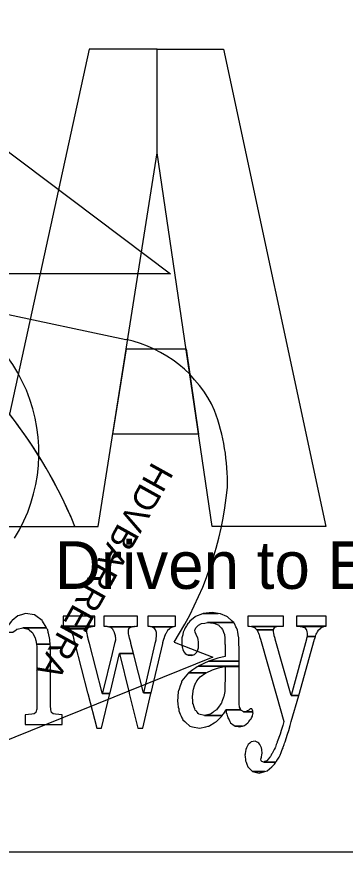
# Model space of a CAD drawing. Extents: x -0.5 to 21.6, y 4.3 to 17.8.
# Drawn here: x 0.949 to 1.229, y 5.937 to 6.651 of the extents above; entities that cross this region are included whole.
import ezdxf

# ---------------------------------------------------------------- set-up
doc = ezdxf.new("R2010")
doc.units = 0
for name, color, linetype in [('DETL-LINE', 7, 'Continuous'), ('TTLB-TEXT', 7, 'Continuous'), ('USER-BORD', 7, 'Continuous')]:
    doc.layers.add(name, color=color, linetype=linetype)

msp = doc.modelspace()

# ---------------------------------------------------------------- linework, layer by layer
at = {"layer": 'DETL-LINE'}
msp.add_line((0.88856, 6.21553), (0.99861, 6.21553), dxfattribs=at)
for points in [[(0.3943, 14.1527), (0.3943, 16.2906), (7.7685, 16.2906), (7.7685, 5.9375), (0.3943, 5.9375), (0.3943, 13.6862)], [(0.99861, 6.21553), (1.01854, 6.21553), (1.0688, 6.53442), (1.0688, 6.62281), (1.01074, 6.62281), (0.94281, 6.31145)]]:
    msp.add_lwpolyline(points, dxfattribs=at)
for points in [[(1.0688, 6.53442), (1.0688, 6.62281), (1.12513, 6.62281), (1.21244, 6.21553), (1.11559, 6.21553)], [(1.04243, 6.36709), (1.09335, 6.36709), (1.10403, 6.29434), (1.03096, 6.29434)], [(0.9395, 6.1274), (0.9384, 6.1254), (0.9456, 6.1254), (0.9484, 6.1274), (0.9492, 6.1279), (0.9494, 6.128), (0.9494, 6.128), (0.9542, 6.129), (0.9744, 6.129), (0.9742, 6.1295), (0.9711, 6.1348), (0.9708, 6.1353), (0.9653, 6.1393), (0.9641, 6.1401), (0.9565, 6.1412), (0.953, 6.1401), (0.95, 6.1393), (0.9452, 6.1353), (0.9445, 6.1348), (0.9406, 6.1295), (0.9403, 6.129), (0.9399, 6.128), (0.9399, 6.1279)], [(1.0939, 6.1062), (1.095, 6.1056), (1.0987, 6.1056), (1.1004, 6.1062), (1.1012, 6.107), (1.1025, 6.1084), (1.1032, 6.1104), (1.1038, 6.112), (1.1038, 6.1126), (1.1038, 6.1144), (1.1039, 6.1153), (1.1039, 6.1153), (1.1039, 6.1154), (1.1039, 6.1164), (1.1035, 6.1194), (1.1033, 6.12), (1.1033, 6.1204), (1.1032, 6.1204), (1.1019, 6.1232), (1.1019, 6.1234), (1.101, 6.1252), (1.101, 6.1252), (1.1008, 6.127), (1.1008, 6.127), (1.101, 6.1276), (1.1015, 6.1289), (1.1025, 6.13), (1.1032, 6.1307), (1.1039, 6.1312), (1.1064, 6.1326), (1.1092, 6.1331), (1.1115, 6.1335), (1.134, 6.1335), (1.1327, 6.1347), (1.1287, 6.1384), (1.128, 6.1387), (1.1225, 6.141), (1.1207, 6.1413), (1.1079, 6.1413), (1.1072, 6.141), (1.1014, 6.1387), (1.1011, 6.1384), (1.0965, 6.1347), (1.0956, 6.1335), (1.0953, 6.1331), (1.0949, 6.1326), (1.0939, 6.1312), (1.0936, 6.1307), (1.093, 6.13), (1.0925, 6.1289), (1.0919, 6.1276), (1.0917, 6.127), (1.0916, 6.127), (1.0909, 6.1252), (1.0908, 6.1252), (1.0905, 6.1234), (1.0905, 6.1232), (1.0898, 6.1204), (1.0898, 6.1204), (1.0898, 6.12), (1.0897, 6.1194), (1.0896, 6.1164), (1.0896, 6.1154), (1.0896, 6.1153), (1.0897, 6.1144), (1.0901, 6.1126), (1.0902, 6.112), (1.0905, 6.1104), (1.0917, 6.1084), (1.0925, 6.107)], [(1.1156, 6.1421), (1.1079, 6.1413), (1.1207, 6.1413)], [(0.9885, 6.1389), (0.9885, 6.1304), (1.0155, 6.1304), (1.0155, 6.1389)], [(1.0275, 6.13), (1.0282, 6.1299), (1.0467, 6.1299), (1.0473, 6.13), (1.0477, 6.1301), (1.0479, 6.1302), (1.0493, 6.1302), (1.0492, 6.1302), (1.0506, 6.1304), (1.0506, 6.1304), (1.0519, 6.1304), (1.0519, 6.1389), (1.0233, 6.1389), (1.0233, 6.1304), (1.0258, 6.1304), (1.0263, 6.1302), (1.0268, 6.1302), (1.027, 6.1301)], [(1.0638, 6.1301), (1.0643, 6.13), (1.0821, 6.13), (1.0823, 6.1301), (1.0826, 6.1302), (1.0832, 6.1302), (1.0838, 6.1304), (1.0844, 6.1304), (1.0844, 6.1389), (1.0608, 6.1389), (1.0608, 6.1304), (1.0624, 6.1304), (1.0629, 6.1302), (1.0635, 6.1302)], [(1.1204, 6.1032), (1.1126, 6.1006), (1.1385, 6.1006), (1.1385, 6.1032), (1.1385, 6.1047), (1.1385, 6.1053), (1.1385, 6.1056), (1.1385, 6.1062), (1.1385, 6.107), (1.1385, 6.1084), (1.1385, 6.1104), (1.1385, 6.112), (1.1385, 6.1126), (1.1384, 6.1144), (1.1384, 6.1153), (1.1384, 6.1154), (1.1384, 6.1164), (1.1383, 6.1194), (1.1383, 6.1194), (1.1383, 6.12), (1.1383, 6.1204), (1.1383, 6.1204), (1.1378, 6.1232), (1.1378, 6.1234), (1.1375, 6.1252), (1.1375, 6.1252), (1.1372, 6.127), (1.1372, 6.127), (1.137, 6.1276), (1.1369, 6.1276), (1.1363, 6.1289), (1.1357, 6.13), (1.1353, 6.1307), (1.1352, 6.1312), (1.1345, 6.1326), (1.1342, 6.1331), (1.134, 6.1335), (1.1115, 6.1335), (1.1168, 6.1331), (1.1179, 6.1326), (1.1212, 6.1312), (1.1216, 6.1307), (1.1223, 6.13), (1.1232, 6.1289), (1.1244, 6.1276), (1.1247, 6.127), (1.1247, 6.127), (1.1253, 6.1252), (1.1253, 6.1252), (1.126, 6.1234), (1.1261, 6.1232), (1.1264, 6.1204), (1.1264, 6.1204), (1.1264, 6.12), (1.1264, 6.1194), (1.1264, 6.1164), (1.1264, 6.1154), (1.1264, 6.1153), (1.1265, 6.1144), (1.1265, 6.1126), (1.1265, 6.112), (1.1265, 6.1104), (1.1265, 6.1084), (1.1265, 6.107), (1.1265, 6.1062), (1.1265, 6.1056), (1.1265, 6.1053), (1.1265, 6.1047)], [(1.1474, 6.1304), (1.149, 6.1302), (1.1705, 6.1302), (1.1706, 6.1304), (1.1727, 6.1304), (1.1763, 6.1305), (1.1763, 6.1389), (1.1458, 6.1389), (1.1458, 6.1305), (1.1458, 6.1304)], [(1.1875, 6.1305), (1.1875, 6.1304), (1.2126, 6.1304), (1.2126, 6.1305), (1.2126, 6.1389), (1.1875, 6.1389)], [(0.9652, 6.1183), (0.9658, 6.1151), (0.9775, 6.1151), (0.9773, 6.1183), (0.9772, 6.1191), (0.977, 6.1204), (0.9763, 6.1232), (0.976, 6.1246), (0.9759, 6.1249), (0.9758, 6.1254), (0.9758, 6.1254), (0.9754, 6.1274), (0.975, 6.1279), (0.975, 6.128), (0.9744, 6.129), (0.9542, 6.129), (0.9588, 6.128), (0.9589, 6.1279), (0.9596, 6.1274), (0.962, 6.1254), (0.9625, 6.1249), (0.9627, 6.1246), (0.9634, 6.1232), (0.9648, 6.1204), (0.965, 6.1191)], [(0.9918, 6.1299), (0.9922, 6.1298), (1.0111, 6.1298), (1.0115, 6.1299), (1.0122, 6.13), (1.0126, 6.1301), (1.0128, 6.1302), (1.0137, 6.1302), (1.0137, 6.1302), (1.0145, 6.1304), (1.0145, 6.1304), (1.0155, 6.1304), (0.9885, 6.1304), (0.9893, 6.1304), (0.9902, 6.1302), (0.9905, 6.1302), (0.9908, 6.1301), (0.9912, 6.13)], [(0.9941, 6.1285), (0.9944, 6.1282), (1.0092, 6.1282), (1.0092, 6.1285), (1.0094, 6.1287), (1.0095, 6.1289), (1.0097, 6.129), (1.0109, 6.1298), (1.0111, 6.1298), (0.9921, 6.1298), (0.9923, 6.1298), (0.9934, 6.129), (0.9935, 6.1289), (0.9937, 6.1287)], [(1.0095, 6.0731), (1.0172, 6.0433), (1.0213, 6.0433), (1.0284, 6.0731), (1.0219, 6.0731), (1.0217, 6.0735), (1.0109, 6.1157), (1.0107, 6.1166), (1.0102, 6.1186), (1.01, 6.1194), (1.0099, 6.1196), (1.0098, 6.12), (1.0094, 6.1219), (1.0093, 6.1221), (1.0092, 6.1226), (1.0089, 6.1241), (1.0087, 6.1245), (1.0087, 6.1248), (1.0087, 6.1253), (1.0087, 6.127), (1.0087, 6.127), (1.0087, 6.1272), (1.0092, 6.1282), (0.9944, 6.1282), (0.9949, 6.1272), (0.995, 6.127), (0.9951, 6.127), (0.9959, 6.1253), (0.996, 6.1248), (0.9961, 6.1245), (0.9963, 6.1241), (0.9968, 6.1226), (0.997, 6.1221), (0.997, 6.1219), (0.9975, 6.12), (0.9976, 6.1196), (0.9976, 6.1194), (0.9978, 6.1186), (0.9984, 6.1166), (0.9986, 6.1157), (1.0094, 6.0735)], [(1.022, 6.0735), (1.0219, 6.0731), (1.0284, 6.0731), (1.0285, 6.0735), (1.0366, 6.1072), (1.0484, 6.1072), (1.0463, 6.1157), (1.0463, 6.1157), (1.0461, 6.1166), (1.0456, 6.1186), (1.0456, 6.1186), (1.0453, 6.1194), (1.0453, 6.1196), (1.0452, 6.12), (1.0448, 6.1219), (1.0447, 6.1221), (1.0446, 6.1226), (1.0443, 6.1241), (1.0442, 6.1245), (1.0442, 6.1248), (1.0442, 6.1253), (1.0442, 6.127), (1.0442, 6.127), (1.0442, 6.1272), (1.0446, 6.1282), (1.0446, 6.1285), (1.0448, 6.1287), (1.045, 6.1289), (1.0451, 6.129), (1.0451, 6.129), (1.0462, 6.1298), (1.0464, 6.1298), (1.0467, 6.1299), (1.0282, 6.1299), (1.0283, 6.1298), (1.0285, 6.1298), (1.0296, 6.129), (1.0298, 6.1289), (1.03, 6.1287), (1.0304, 6.1285), (1.0305, 6.1282), (1.031, 6.1272), (1.0311, 6.127), (1.0312, 6.127), (1.0319, 6.1253), (1.0321, 6.1248), (1.0322, 6.1245), (1.0323, 6.1241), (1.0328, 6.1226), (1.0329, 6.1221), (1.0329, 6.1219), (1.0333, 6.12), (1.0334, 6.1196), (1.0333, 6.1194), (1.0331, 6.1186), (1.0326, 6.1166), (1.0324, 6.1157), (1.0303, 6.1072)], [(1.0667, 6.1157), (1.057, 6.0735), (1.0635, 6.0735), (1.0734, 6.1157), (1.0736, 6.1166), (1.0741, 6.1186), (1.0743, 6.1194), (1.0743, 6.1194), (1.0744, 6.1196), (1.0745, 6.12), (1.0753, 6.1219), (1.0753, 6.1221), (1.0756, 6.1226), (1.0755, 6.1226), (1.0762, 6.1241), (1.0764, 6.1245), (1.0764, 6.1245), (1.0765, 6.1248), (1.0768, 6.1253), (1.0778, 6.127), (1.0779, 6.127), (1.0779, 6.1272), (1.0792, 6.1282), (1.0795, 6.1285), (1.0798, 6.1287), (1.0799, 6.1289), (1.0801, 6.129), (1.0816, 6.1298), (1.0817, 6.1298), (1.0819, 6.1299), (1.0821, 6.13), (1.0643, 6.13), (1.0645, 6.1299), (1.0646, 6.1298), (1.0647, 6.1298), (1.0659, 6.129), (1.066, 6.1289), (1.0661, 6.1287), (1.0663, 6.1285), (1.0664, 6.1282), (1.0671, 6.1272), (1.0671, 6.127), (1.0672, 6.127), (1.0677, 6.1253), (1.0679, 6.1248), (1.0679, 6.1245), (1.0679, 6.1241), (1.0679, 6.1226), (1.0679, 6.1221), (1.0679, 6.1219), (1.0676, 6.12), (1.0675, 6.1196), (1.0675, 6.1194), (1.0674, 6.1186), (1.0669, 6.1166)], [(1.1534, 6.1276), (1.1538, 6.1272), (1.1678, 6.1272), (1.1679, 6.1276), (1.1686, 6.1291), (1.1686, 6.1293), (1.1687, 6.1293), (1.1689, 6.1296), (1.1697, 6.13), (1.1705, 6.1302), (1.149, 6.1302), (1.1498, 6.13), (1.1507, 6.1296), (1.1518, 6.1293), (1.1518, 6.1293), (1.152, 6.1291)], [(1.1605, 6.0149), (1.1595, 6.0145), (1.1698, 6.0145), (1.1701, 6.0149), (1.1705, 6.0156), (1.1707, 6.0159), (1.1714, 6.017), (1.1725, 6.0188), (1.1728, 6.0193), (1.1734, 6.0205), (1.1738, 6.0211), (1.1741, 6.0219), (1.1753, 6.0253), (1.1759, 6.0267), (1.1758, 6.0267), (1.176, 6.0271), (1.1769, 6.0294), (1.1773, 6.0306), (1.1775, 6.0311), (1.1777, 6.0317), (1.1798, 6.0384), (1.1808, 6.0415), (1.182, 6.0458), (1.1829, 6.049), (1.1829, 6.049), (1.1893, 6.0714), (1.1829, 6.0714), (1.1692, 6.1194), (1.1692, 6.1196), (1.1691, 6.1196), (1.1691, 6.12), (1.1686, 6.1216), (1.1685, 6.1219), (1.1683, 6.123), (1.1681, 6.1237), (1.168, 6.1244), (1.168, 6.1246), (1.1678, 6.1256), (1.1678, 6.1271), (1.1678, 6.1272), (1.1538, 6.1272), (1.1538, 6.1271), (1.1545, 6.1256), (1.155, 6.1246), (1.1551, 6.1244), (1.1553, 6.1237), (1.1556, 6.123), (1.156, 6.1219), (1.156, 6.1216), (1.1565, 6.12), (1.1566, 6.1196), (1.1567, 6.1194), (1.1703, 6.0714), (1.1766, 6.049), (1.1758, 6.0458), (1.1744, 6.0415), (1.1735, 6.0384), (1.171, 6.0317), (1.1708, 6.0311), (1.1706, 6.0306), (1.1701, 6.0294), (1.1694, 6.0271), (1.1691, 6.0267), (1.1684, 6.0253), (1.1666, 6.0219), (1.1662, 6.0211), (1.1659, 6.0205), (1.1653, 6.0193), (1.1648, 6.0188), (1.1632, 6.017), (1.1623, 6.0159), (1.162, 6.0156)], [(1.189, 6.1304), (1.1905, 6.1302), (1.2107, 6.1302), (1.2116, 6.1304), (1.2126, 6.1304), (1.1875, 6.1304)], [(1.1964, 6.1219), (1.1964, 6.1216), (1.2036, 6.1216), (1.2037, 6.1219), (1.204, 6.123), (1.2042, 6.1237), (1.2046, 6.1244), (1.2047, 6.1246), (1.2053, 6.1256), (1.2061, 6.1271), (1.2062, 6.1272), (1.2067, 6.1276), (1.2083, 6.1291), (1.2084, 6.1293), (1.2085, 6.1293), (1.2085, 6.1293), (1.2093, 6.1296), (1.21, 6.13), (1.2107, 6.1302), (1.1905, 6.1302), (1.1923, 6.13), (1.1931, 6.1296), (1.1941, 6.1293), (1.1942, 6.1293), (1.1945, 6.1291), (1.1957, 6.1276), (1.196, 6.1272), (1.196, 6.1271), (1.1963, 6.1256), (1.1965, 6.1246), (1.1965, 6.1244), (1.1965, 6.1237), (1.1965, 6.123)], [(1.1959, 6.1194), (1.1829, 6.0714), (1.1893, 6.0714), (1.2028, 6.1194), (1.2029, 6.1196), (1.203, 6.12), (1.2036, 6.1216), (1.1964, 6.1216), (1.196, 6.12), (1.196, 6.1196)], [(0.9563, 6.0549), (0.9563, 6.0465), (0.9877, 6.0465), (0.9877, 6.0549), (0.9821, 6.0553), (0.9801, 6.0556), (0.9787, 6.0567), (0.978, 6.059), (0.978, 6.059), (0.978, 6.0593), (0.978, 6.0593), (0.9778, 6.0626), (0.9778, 6.0956), (0.9778, 6.1029), (0.9778, 6.1094), (0.9778, 6.1102), (0.9778, 6.1102), (0.9778, 6.1106), (0.9777, 6.1127), (0.9775, 6.1151), (0.9658, 6.1151), (0.966, 6.1127), (0.9661, 6.1106), (0.9662, 6.1102), (0.9662, 6.1094), (0.9662, 6.1029), (0.9662, 6.0956), (0.9662, 6.0626), (0.966, 6.0593), (0.9659, 6.059), (0.9659, 6.059), (0.9653, 6.0567), (0.9639, 6.0556), (0.9618, 6.0553)], [(1.0449, 6.0731), (1.0522, 6.0433), (1.0564, 6.0433), (1.0633, 6.0731), (1.0635, 6.0735), (1.057, 6.0735), (1.0484, 6.1072), (1.0366, 6.1072), (1.0448, 6.0735)], [(1.095, 6.1056), (1.0978, 6.1053), (1.0987, 6.1056)], [(1.0956, 6.0907), (1.0953, 6.0906), (1.1102, 6.0906), (1.1105, 6.0907), (1.1159, 6.0932), (1.121, 6.0949), (1.1247, 6.0958), (1.1265, 6.0961), (1.1385, 6.0961), (1.1385, 6.0964), (1.1036, 6.0964), (1.1033, 6.0961), (1.1028, 6.0958), (1.1015, 6.0949), (1.0991, 6.0932)], [(1.1126, 6.1006), (1.1036, 6.0964), (1.1385, 6.0964), (1.1385, 6.1006)], [(1.0988, 6.0446), (1.1048, 6.0433), (1.1102, 6.0446), (1.1121, 6.0451), (1.1126, 6.0452), (1.1126, 6.0452), (1.1135, 6.0458), (1.1173, 6.048), (1.1182, 6.0485), (1.1182, 6.0485), (1.1191, 6.049), (1.1206, 6.0505), (1.1214, 6.0513), (1.1224, 6.0523), (1.1237, 6.0536), (1.1238, 6.0537), (1.1242, 6.0543), (1.1091, 6.0543), (1.1043, 6.0554), (1.1042, 6.0556), (1.1037, 6.056), (1.103, 6.0568), (1.1028, 6.057), (1.1025, 6.0573), (1.1024, 6.0575), (1.1021, 6.0578), (1.1018, 6.0581), (1.1013, 6.0586), (1.101, 6.0589), (1.101, 6.0589), (1.1007, 6.0598), (1.1007, 6.0598), (1.1002, 6.0614), (1.0993, 6.0643), (1.0992, 6.0643), (1.0992, 6.0644), (1.0992, 6.0648), (1.0991, 6.0662), (1.0991, 6.0666), (1.0988, 6.07), (1.0988, 6.0704), (1.0993, 6.0748), (1.0994, 6.0753), (1.0996, 6.0768), (1.1005, 6.0794), (1.1016, 6.0824), (1.1021, 6.083), (1.1026, 6.0837), (1.1052, 6.0871), (1.1102, 6.0906), (1.0953, 6.0906), (1.0925, 6.0871), (1.0897, 6.0837), (1.0895, 6.083), (1.0893, 6.0824), (1.0882, 6.0794), (1.0873, 6.0768), (1.0868, 6.0753), (1.0867, 6.0748), (1.0864, 6.0704), (1.0864, 6.07), (1.0861, 6.0666), (1.0861, 6.0662), (1.0863, 6.0648), (1.0864, 6.0644), (1.0864, 6.0643), (1.0867, 6.0614), (1.087, 6.0598), (1.087, 6.0598), (1.0871, 6.0589), (1.0871, 6.0589), (1.0871, 6.0586), (1.0872, 6.0581), (1.0872, 6.0578), (1.0874, 6.0575), (1.0875, 6.0573), (1.0876, 6.057), (1.0876, 6.0568), (1.088, 6.056), (1.0883, 6.0556), (1.0883, 6.0554), (1.0888, 6.0543), (1.0891, 6.0537), (1.0892, 6.0536), (1.0898, 6.0523), (1.0902, 6.0513), (1.0906, 6.0505), (1.0922, 6.049), (1.0927, 6.0485), (1.0933, 6.048), (1.0958, 6.0458), (1.0964, 6.0452), (1.0964, 6.0452), (1.0966, 6.0451)], [(1.1138, 6.0554), (1.1091, 6.0543), (1.1242, 6.0543), (1.125, 6.0554), (1.1251, 6.0556), (1.1251, 6.0556), (1.1254, 6.056), (1.126, 6.0568), (1.1262, 6.057), (1.1263, 6.0573), (1.1263, 6.0573), (1.1264, 6.0575), (1.1265, 6.0578), (1.1265, 6.0578), (1.1267, 6.0581), (1.127, 6.0586), (1.1271, 6.0589), (1.1272, 6.0589), (1.1272, 6.0589), (1.1273, 6.0592), (1.14, 6.0592), (1.1397, 6.0598), (1.1397, 6.0598), (1.1397, 6.0598), (1.1389, 6.0614), (1.1385, 6.0643), (1.1385, 6.0644), (1.1385, 6.0644), (1.1385, 6.0648), (1.1385, 6.0648), (1.1385, 6.0662), (1.1385, 6.0666), (1.1385, 6.07), (1.1385, 6.0704), (1.1385, 6.0748), (1.1385, 6.0753), (1.1385, 6.0768), (1.1385, 6.0794), (1.1385, 6.0824), (1.1385, 6.083), (1.1385, 6.0837), (1.1385, 6.0871), (1.1385, 6.0906), (1.1385, 6.0907), (1.1385, 6.0932), (1.1385, 6.0949), (1.1385, 6.0958), (1.1385, 6.0961), (1.1265, 6.0961), (1.1265, 6.0958), (1.1265, 6.0949), (1.1265, 6.0932), (1.1265, 6.0907), (1.1265, 6.0906), (1.1265, 6.0871), (1.1265, 6.0837), (1.1265, 6.083), (1.1264, 6.0824), (1.1264, 6.0794), (1.1263, 6.0768), (1.1262, 6.0753), (1.1262, 6.0748), (1.1254, 6.0704), (1.1253, 6.07), (1.124, 6.0666), (1.1239, 6.0662), (1.1234, 6.0648), (1.1231, 6.0644), (1.123, 6.0643), (1.121, 6.0614), (1.1199, 6.0598), (1.1199, 6.0598), (1.1192, 6.0592), (1.1188, 6.0589), (1.1187, 6.0589), (1.1183, 6.0586), (1.1178, 6.0581), (1.1174, 6.0578), (1.1169, 6.0575), (1.1167, 6.0573), (1.1163, 6.057), (1.116, 6.0568), (1.1151, 6.056), (1.1145, 6.0556)], [(1.1342, 6.0458), (1.1349, 6.0452), (1.1413, 6.0452), (1.1432, 6.0458), (1.1459, 6.048), (1.1466, 6.0485), (1.1469, 6.049), (1.148, 6.0505), (1.1487, 6.0513), (1.1491, 6.0523), (1.1498, 6.0536), (1.1498, 6.0537), (1.1499, 6.0543), (1.1499, 6.0543), (1.1502, 6.0554), (1.1502, 6.0556), (1.1504, 6.056), (1.1503, 6.0568), (1.1503, 6.057), (1.1503, 6.0573), (1.1423, 6.0573), (1.142, 6.0575), (1.1414, 6.0578), (1.141, 6.0581), (1.1403, 6.0586), (1.1402, 6.0589), (1.1401, 6.0589), (1.14, 6.0592), (1.1273, 6.0592), (1.1273, 6.0589), (1.1273, 6.0589), (1.1274, 6.0586), (1.1275, 6.0581), (1.1275, 6.0578), (1.1276, 6.0575), (1.1276, 6.0573), (1.1276, 6.057), (1.1276, 6.0568), (1.1278, 6.056), (1.128, 6.0556), (1.128, 6.0554), (1.1283, 6.0543), (1.1285, 6.0537), (1.1286, 6.0536), (1.1289, 6.0523), (1.1294, 6.0513), (1.1299, 6.0505), (1.1307, 6.049), (1.131, 6.0485), (1.1313, 6.048)], [(1.1445, 6.0575), (1.1423, 6.0573), (1.1503, 6.0573), (1.1503, 6.0575), (1.1502, 6.0578), (1.1502, 6.0581), (1.15, 6.0586), (1.1498, 6.0589), (1.1498, 6.0589), (1.1494, 6.0598), (1.149, 6.0598), (1.1482, 6.0599), (1.148, 6.0598), (1.148, 6.0598), (1.1469, 6.0589), (1.1468, 6.0589), (1.1463, 6.0586), (1.1455, 6.0581), (1.1451, 6.0578)], [(1.1359, 6.0451), (1.1392, 6.0446), (1.1408, 6.0451), (1.1411, 6.0452), (1.1413, 6.0452), (1.1349, 6.0452), (1.1352, 6.0452)], [(1.1494, 6.0069), (1.1499, 6.0063), (1.1603, 6.0063), (1.1624, 6.0069), (1.1664, 6.0105), (1.1687, 6.0126), (1.1698, 6.0145), (1.1595, 6.0145), (1.1579, 6.0149), (1.1574, 6.0156), (1.1572, 6.0159), (1.1571, 6.017), (1.1576, 6.0188), (1.1577, 6.0193), (1.1579, 6.0205), (1.158, 6.0211), (1.1581, 6.0219), (1.1578, 6.0253), (1.1578, 6.0253), (1.1576, 6.0267), (1.1574, 6.0271), (1.1561, 6.0294), (1.1554, 6.0306), (1.1544, 6.0311), (1.1532, 6.0317), (1.1522, 6.0322), (1.1522, 6.0322), (1.1488, 6.0317), (1.1481, 6.0311), (1.1475, 6.0306), (1.1461, 6.0294), (1.1451, 6.0271), (1.1449, 6.0267), (1.1443, 6.0253), (1.1438, 6.0219), (1.1436, 6.0211), (1.1435, 6.0205), (1.1436, 6.0193), (1.1437, 6.0188), (1.1439, 6.017), (1.144, 6.0159), (1.144, 6.0156), (1.1443, 6.0149), (1.1444, 6.0145), (1.1451, 6.0126), (1.1459, 6.0105)], [(1.1499, 6.0063), (1.1556, 6.005), (1.1603, 6.0063)]]:
    msp.add_lwpolyline(points, close=True, dxfattribs=at)
for end in [60.71026, 38.08951]:
    msp.add_arc((0.62514, 6.06246), 0.40363, 22.28728, end, dxfattribs=at)
at = {"layer": 'TTLB-TEXT'}
msp.add_line((7.7685, 5.9375), (0.3943, 5.9375), dxfattribs=at)
msp.add_lwpolyline([(0.3943, 16.2906), (7.7685, 16.2906), (7.7685, 5.9375), (0.3943, 5.9375)], close=True, dxfattribs=at)
at = {"layer": 'USER-BORD'}
for p, q in [((0.8206, 6.6268), (1.0801, 6.4312)), ((1.0801, 6.4312), (0.8027, 6.4312)), ((0.8605, 6.4135), (1.0421, 6.3751)), ((1.0833, 6.1168), (1.116, 6.1039)), ((1.116, 6.1039), (0.8149, 5.9822)), ((7.7685, 5.9375), (0.3943, 5.9375))]:
    msp.add_line(p, q, dxfattribs=at)
for centre, major_axis, start_param, end_param in [((0.82951, 6.27835), (0, -0.13842), 1.0171, 2.916019), ((1.01986, 6.27006), (0, 0.10736), 5.137679, 6.073798), ((0.94665, 6.25219), (0, -0.18197), 1.552562, 1.919461), ((0.82987, 6.27774), (0, -0.30012), 1.005137, 1.474454)]:
    msp.add_ellipse(centre, major_axis=major_axis, ratio=0.999903, start_param=start_param, end_param=end_param, dxfattribs=at)

# ---------------------------------------------------------------- texts
at = {"layer": 'DETL-LINE'}
msp.add_text('Driven to Excel', height=0.0406098, dxfattribs=at).set_placement((0.98151, 6.1623))
at = {"layer": 'USER-BORD'}
msp.add_text('HDVBARREIRA', height=0.0211554, rotation=240.96457, dxfattribs=at).set_placement((1.0647, 6.2715))

doc.saveas('drawing.dxf')
